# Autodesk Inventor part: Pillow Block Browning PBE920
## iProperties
Author: ARennick
Shininess: 41.0
PropertySet Name: _Private Model Information
Created: 2001-04
Part Number: Pillow Block Browning PBE920
Document SubType Name: Modeling
Designer: ARennick
Description: Pillow Block Tapered Bearing 1.500 Bore
Vendor: Browning
Control State: 0
Master: False
Checked Out: False
PropertySet Name: Design Tracking Control
Density: 0.0
Volumn: 0.0
Area: 0.0
PropertySet Name: Model Information
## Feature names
1. Extrusion1
2. Extrusion2
3. Extrusion3
4. Extrusion4
5. Extrusion5
6. Extrusion6
7. Mirror1
8. Fillet1
9. Fillet2
